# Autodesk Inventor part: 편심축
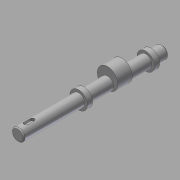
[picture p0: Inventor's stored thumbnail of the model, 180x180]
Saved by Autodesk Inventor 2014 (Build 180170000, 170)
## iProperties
Created: 2016-02
Part Number: 편심축
Material: 강철, 연강
Document SubType Name: Modeling
Designer: mduedu
Density: 7.86 g/cm^3
Appearance: 강철
Mass: 154.534 g
Surface Area: 68.81 cm^2
Volume: 19.6608 cm^3
Author: mduedu
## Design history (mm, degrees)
sketch "스케치1"
  geometry: C1 r 6 at (0, 0); 1 further point
  constraints: 1 centre point, 1 coincident
  dimensions: "d0" = 12 diameter of C1
extrude "돌출1" new body sketch "스케치1" distance "d1" = 140; taper "d2" = 0 deg
chamfer "모따기1" distance "d3" = 1; stored, may be unused: second distance "d4" = 2, angle "d5" = 45 deg
node "작업 평면1"
sketch "스케치2"
  geometry: C1 r 10 at (0, 4); C2 r 6 at (0, 0) reference; 1 further point
  constraints: 1 centre point, 1 tangent, 1 vertical alignment
  dimensions: "d7" = 20 diameter of C1
extrude "돌출2" join sketch "스케치2" stored distance "d8" = 14; taper "d9" = 0 deg
node "작업 평면2"
sketch "스케치3"
  geometry: C1 r 8.5 at (0, 0); 1 further point
  constraints: 1 centre point, 1 coincident
  dimensions: "d12" = 17 diameter of C1
extrude "돌출3" join sketch "스케치3" distance "d13" = 5; taper "d14" = 0 deg
node "작업 평면3"
sketch "스케치4"
  geometry: L1 (-5, 140)-(5, 140) reference; L2 (0, 140)-(0, 0); L3 (-2, 132)-(-2, 126); L4 (2, 126)-(2, 132); A1 r 2 centre (0, 132) between (2, 132) and (-2, 132); A2 r 2 centre (0, 126) between (-2, 126) and (2, 126)
  constraints: 6 end point, 4 point on circle, 4 tangent, 2 centre point, 2 point on line, 1 midpoint, 1 parallel, 1 perpendicular
  dimensions: "d15" = 4 distance between parallel lines of L3 L4; "d17" = 6 distance edge to line of A1 L1; "d18" = 10 dimension on A2 A1
extrude "돌출4" cut sketch "스케치4" distance "d19" = 2.5; taper "d20" = 0 deg
sketch "스케치5"
  geometry: L1 (6, 53)-(6, 139) reference; L2 (-6, 53)-(-6, 139) reference; L3 (6, 115)-(-6, 115); L4 (-5, 140)-(5, 140) reference; L5 (6, 116.5)-(4.5, 115); L6 (6, 116.5)-(6, 115); L7 (4.5, 115)-(6, 115); 1 further point
  constraints: 8 end point, 4 point on line, 2 collinear, 1 perpendicular
  dimensions: "d21" = 25 distance between parallel lines of L3 L4; "d22" = 3 diameter of L5.start L3; "d24" = 45 deg angle of L3 L5
revolve "회전1" sketch "스케치5" stored, may be unused: angle "d25" = 90 deg
sketch "스케치6"
  geometry: L1 (6, 116.5)-(4.5, 115) reference; L2 (6, 113.5)-(4.5, 115) reference; 2 further points
  constraints: 1 coincident
node "작업 평면4"
sketch "스케치7"
  geometry: C1 r 8.5 at (0, -4); 1 further point
  constraints: 1 centre point, 1 coincident
  dimensions: "d27" = 17 diameter of C1
extrude "돌출5" join sketch "스케치7" distance "d29" = 5; taper "d30" = 0 deg
node "솔리드1"
other parameters: "d6" = -46, "d11" = -11, "d26" = 28
